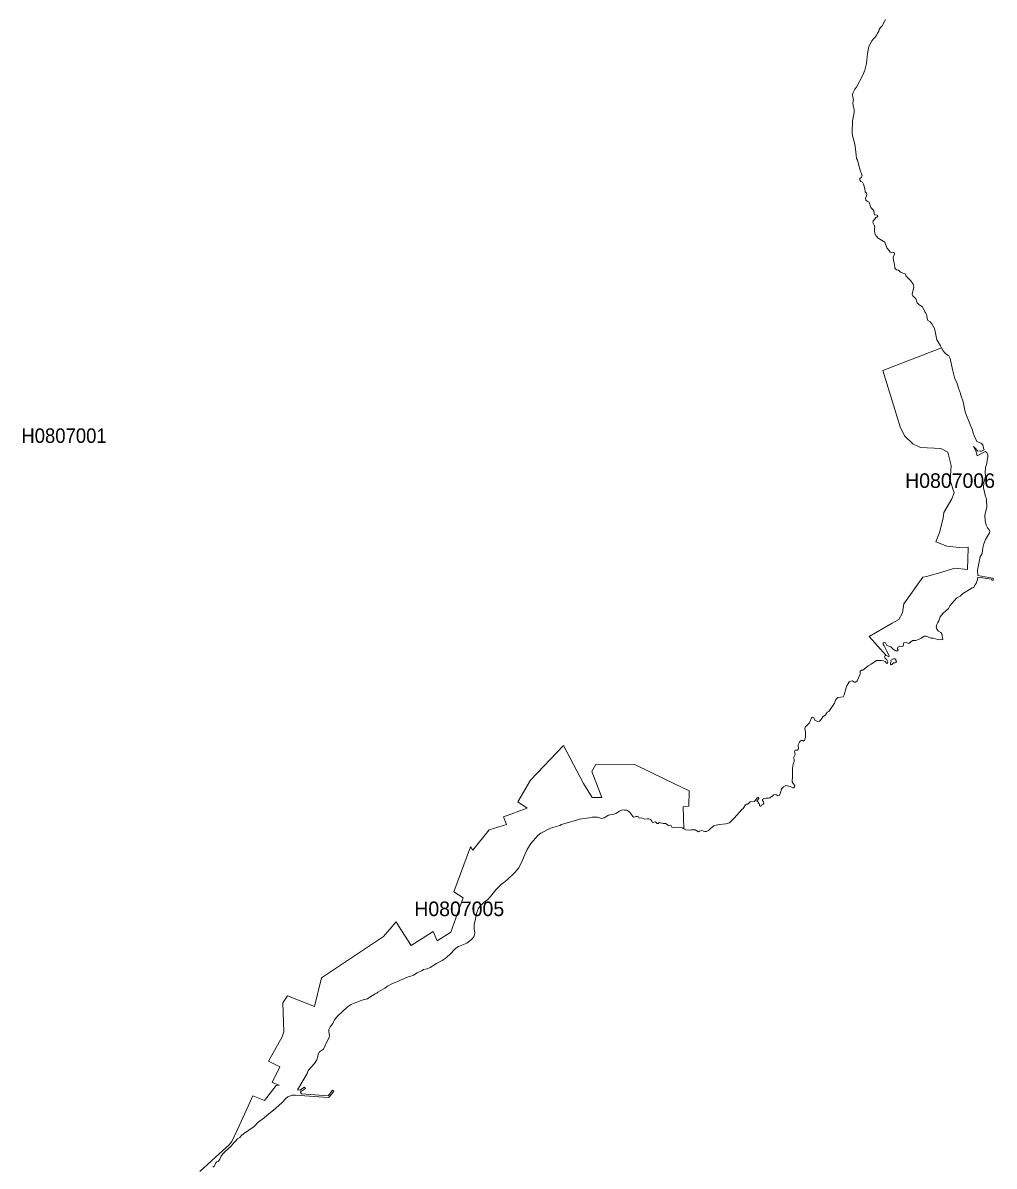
# Model space of a CAD drawing. Extents: x 369010 to 739155, y 6377141 to 6616555.
# Drawn here: x 386985 to 393656, y 6424081 to 6431932 of the extents above; entities that cross this region are included whole.
import ezdxf
from ezdxf.enums import TextEntityAlignment as Align

# ---------------------------------------------------------------- set-up
doc = ezdxf.new("R2010")
doc.units = 0
doc.header["$LTSCALE"] = 40
doc.layers.add('1', color=7, linetype='Continuous', lineweight=13)
doc.layers.add('2', color=7, linetype='Continuous')

msp = doc.modelspace()

# ---------------------------------------------------------------- linework, layer by layer
at = {"layer": '1'}
for points in [[(392739.34, 6430841.74), (392732.06, 6430851.17), (392733.88, 6430862.1), (392745.63, 6430872.19), (392748.78, 6430882.12), (392732.39, 6430927.14), (392716.83, 6430988.87), (392710.38, 6431001.12), (392706.41, 6431045.14), (392698.63, 6431098.27), (392682.24, 6431155.2), (392679.6, 6431181.35), (392682.91, 6431256.33), (392693.83, 6431318.56), (392694.82, 6431339.91), (392687.04, 6431363.08), (392685.39, 6431382.28), (392690.52, 6431406.11), (392686.05, 6431421.67), (392683.07, 6431438.22), (392687.04, 6431454.6), (392698.63, 6431476.94), (392711.21, 6431490.18), (392752.75, 6431572.11), (392767.81, 6431608.02), (392779.23, 6431652.87), (392785.68, 6431721.23), (392795.45, 6431770.38), (392814.81, 6431808.61), (392826.73, 6431822.52), (392837.16, 6431830.79), (392849.4, 6431848.67), (392853.54, 6431861.91), (392863.3, 6431875.15), (392866.45, 6431886.23), (392874.23, 6431899.14), (392887.47, 6431912.05), (392908.82, 6431955.08)], [(392797.1, 6427717.69), (392955.16, 6427810.53), (393000.67, 6427834.53), (393025.33, 6427880.87), (393036.42, 6427942.27), (393165.02, 6428126.65), (393190.51, 6428129.29), (393288.48, 6428157.6), (393382.66, 6428187.55), (393472.03, 6428178.61), (393478.32, 6428324.26), (393477.99, 6428332.7), (393414.43, 6428328.89), (393330.03, 6428338.99), (393255.55, 6428367.45), (393279.38, 6428431.5), (393304.54, 6428531.63), (393310.33, 6428570.53), (393364.45, 6428663.21), (393381, 6428703.92), (393352.87, 6428788.66), (393360.64, 6428891.61), (393337.14, 6428983.13), (393288.65, 6429009.94), (393148.8, 6429016.73), (393097.16, 6429041.72), (393040.56, 6429096.17), (393010.77, 6429157.9), (392890.78, 6429543.86), (393294.11, 6429699.93), (393294.28, 6429699.93), (393287, 6429713.17), (393272.27, 6429742.3), (393261.34, 6429756.2), (393251.25, 6429812.14), (393245.12, 6429833.82), (393228.74, 6429864.44), (393215.99, 6429878.17), (393199.61, 6429887.94), (393193.49, 6429913.1), (393193.49, 6429923.85), (393187.03, 6429937.59), (393178.59, 6429948.35), (393163.2, 6429982.94), (393140.03, 6429995.68), (393126.46, 6430008.59), (393118.35, 6430036.07), (393097.16, 6430056.42), (393093.19, 6430069.83), (393099.48, 6430098.3), (393102.95, 6430119.31), (393100.47, 6430137.52), (393084.25, 6430160.52), (393050.49, 6430192.63), (393045.03, 6430209.02), (393027.98, 6430212.66), (393013.42, 6430220.11), (392999.68, 6430233.02), (392984.62, 6430235.33), (392972.87, 6430248.57), (392972.21, 6430275.05), (392965.09, 6430301.2), (392961.95, 6430324.54), (392970.39, 6430341.09), (392970.72, 6430349.36), (392963.93, 6430354), (392951.85, 6430352.67), (392940.93, 6430356.81), (392931.49, 6430372.04), (392919.25, 6430387.93), (392904.02, 6430425.5), (392858.84, 6430454.29), (392845.76, 6430470.02), (392837.16, 6430485.24), (392833.51, 6430503.45), (392833.18, 6430519.83), (392835.5, 6430532.25), (392832.52, 6430543.83), (392823.25, 6430561.87), (392823.91, 6430573.29), (392834.84, 6430582.73), (392841.95, 6430594.64), (392850.4, 6430597.79), (392857.18, 6430604.9), (392854.2, 6430610.53), (392834.84, 6430614.67), (392828.38, 6430639), (392822.92, 6430649.59), (392808.69, 6430663.82), (392797.93, 6430700.73), (392783.7, 6430706.52), (392775.42, 6430714.63), (392773.11, 6430725.89), (392781.88, 6430750.22), (392778.24, 6430762.13), (392770.13, 6430771.57), (392766.65, 6430794.9), (392757.22, 6430825.19), (392750.76, 6430836.94), (392739.34, 6430841.74)], [(393294.28, 6429699.93), (393294.11, 6429699.93), (392890.78, 6429543.86), (393010.77, 6429157.9), (393040.56, 6429096.17), (393097.16, 6429041.72), (393148.8, 6429016.73), (393288.65, 6429009.94), (393337.14, 6428983.13), (393360.64, 6428891.61), (393352.87, 6428788.66), (393381, 6428703.92), (393364.45, 6428663.21), (393310.33, 6428570.53), (393304.54, 6428531.63), (393279.38, 6428431.5), (393255.55, 6428367.45), (393330.03, 6428338.99), (393414.43, 6428328.89), (393477.99, 6428332.7), (393478.32, 6428324.26), (393472.03, 6428178.61), (393382.66, 6428187.55), (393288.48, 6428157.6), (393190.51, 6428129.29), (393165.02, 6428126.65), (393036.42, 6427942.27), (393025.33, 6427880.87), (393000.67, 6427834.53), (392955.16, 6427810.53), (392797.1, 6427717.69), (392914.61, 6427587.6), (392916.27, 6427587.6), (392932.65, 6427577.83), (392935.13, 6427584.46), (392924.71, 6427600.84), (392918.91, 6427617.39), (392900.71, 6427653.47), (392893.43, 6427662.41), (392893.26, 6427673.33), (392900.71, 6427676.48), (392908.98, 6427673.66), (392919.25, 6427656.28), (392945.73, 6427648.34), (392961.95, 6427631.46), (392980.65, 6427620.2), (392993.39, 6427619.71), (392995.54, 6427626.33), (392992.4, 6427633.28), (392993.39, 6427644.2), (393006.96, 6427650.82), (393022.52, 6427650.16), (393029.8, 6427652.81), (393032.28, 6427668.53), (393036.26, 6427674.82), (393049.17, 6427676.14), (393069.52, 6427669.19), (393094.84, 6427691.37), (393117.85, 6427690.38), (393128.77, 6427696.34), (393156.41, 6427705.93), (393169.65, 6427718.68), (393174.62, 6427720.66), (393189.68, 6427720.5), (393220.96, 6427707.76), (393237.18, 6427706.43), (393269.45, 6427696.83), (393292.13, 6427694.85), (393303.55, 6427697.83), (393297.26, 6427736.39), (393290.14, 6427746.32), (393274.25, 6427754.43), (393261.18, 6427768.16), (393258.53, 6427784.22), (393262.17, 6427800.11), (393267.96, 6427815), (393275.74, 6427826.42), (393286, 6427852.74), (393306.03, 6427878.39), (393341.45, 6427911.33), (393352.37, 6427928.04), (393397.88, 6427980.67), (393421.55, 6427995.9), (393437.93, 6428010.46), (393504.14, 6428052.67), (393515.23, 6428055.48), (393522.51, 6428069.71), (393531.44, 6428082.46), (393542.37, 6428109.76), (393544.19, 6428125.32), (393638.36, 6428111.09), (393640.68, 6428104.97), (393648.79, 6428104.14), (393649.78, 6428118.87), (393619.99, 6428122.67), (393544.68, 6428136.91), (393541.54, 6428173.15), (393560.24, 6428264.84), (393572.82, 6428288.67), (393577.95, 6428327.24)], [(393577.95, 6428327.24), (393584.41, 6428354.21), (393596.82, 6428385), (393624.62, 6428430.01), (393626.94, 6428439.28), (393622.31, 6428451.36), (393609.23, 6428465.43), (393601.78, 6428483.31), (393593.67, 6428512.93), (393591.19, 6428550.34), (393606.42, 6428607.6), (393603.77, 6428657.25), (393600.96, 6428670), (393596.32, 6428679.59), (393581.59, 6428739.18), (393584.24, 6428775.42), (393591.85, 6428799.59), (393595.49, 6428818.12), (393593.01, 6428844.6), (393596.32, 6428878.2), (393605.92, 6428906.17), (393608.07, 6428931), (393612.21, 6428946.22), (393612.04, 6428962.44), (393605.09, 6428980.81), (393593.67, 6428987.43), (393538.23, 6428958.8), (393536.08, 6428970.88), (393528.8, 6428993.72), (393513.57, 6429021.86), (393525.82, 6429012.42), (393540.55, 6428993.39), (393558.92, 6428989.91), (393568.68, 6428990.74), (393587.55, 6429001), (393581.59, 6429010.44), (393577.29, 6429034.27), (393566.37, 6429045.52), (393536.24, 6429056.78), (393520.69, 6429091.04), (393508.94, 6429123.15), (393506.62, 6429135.56), (393466.24, 6429234.86), (393457.46, 6429260.35), (393443.07, 6429330.19), (393425.69, 6429374.38), (393424.86, 6429386.63), (393409.96, 6429424.03), (393399.54, 6429461.93), (393385.97, 6429487.42), (393369.08, 6429551.97), (393353.69, 6429627.6), (393344.92, 6429644.81), (393336.15, 6429649.61), (393316.79, 6429665.34), (393306.03, 6429678.74), (393294.28, 6429699.93)], [(392044.56, 6426568.59), (392044.39, 6426556.51), (392048.36, 6426553.03), (392055.31, 6426553.53), (392060.94, 6426561.31), (392069.05, 6426566.61), (392074.35, 6426574.22), (392071.53, 6426583.32), (392064.25, 6426591.1), (392065.41, 6426599.54), (392071.37, 6426604.34), (392089.41, 6426606.99), (392097.35, 6426609.14), (392105.3, 6426608.48), (392114.07, 6426611.13), (392131.78, 6426621.39), (392142.2, 6426630.32), (392155.11, 6426632.48), (392169.18, 6426623.7), (392179.77, 6426625.69), (392187.72, 6426642.9), (392194.67, 6426671.37), (392207.91, 6426685.27), (392225.29, 6426695.86), (392254.42, 6426687.92), (392271.96, 6426678.49), (392280.4, 6426679.81), (392285.53, 6426686.1), (392286.36, 6426695.86), (392275.1, 6426708.77), (392268.32, 6426720.52), (392270.97, 6426758.92), (392271.46, 6426814.53), (392275.77, 6426841.18), (392281.23, 6426860.71), (392281.23, 6426874.94), (392277.75, 6426885.86), (392289.01, 6426908.21), (392285.03, 6426927.57), (392289.01, 6426937.83), (392304.73, 6426938.33), (392312.84, 6426946.77), (392309.69, 6426974.24), (392318.13, 6426992.94), (392325.58, 6427001.05), (392331.04, 6427004.36), (392340.81, 6427004.2), (392346.77, 6426999.4), (392352.72, 6427003.04), (392359.68, 6427026.71), (392361, 6427060.3), (392356.37, 6427085.79), (392358.35, 6427095.56), (392387.48, 6427126.01), (392401.71, 6427160.27), (392407.84, 6427164.74), (392413.96, 6427162.75), (392427.37, 6427142.39), (392444.41, 6427134.95), (392455.17, 6427137.76), (392467.42, 6427148.52), (392478.84, 6427166.39), (392497.04, 6427181.12), (392509.46, 6427199), (392519.22, 6427203.63), (392558.45, 6427260.56), (392566.89, 6427281.42), (392573.01, 6427289.53), (392581.45, 6427298.3), (392618.19, 6427304.42), (392625.97, 6427316.84), (392636.07, 6427359.37), (392643.85, 6427380.22), (392660.73, 6427406.7), (392669.5, 6427412.33), (392681.91, 6427412.66), (392693.83, 6427404.22), (392702.6, 6427404.55), (392714.19, 6427412.99), (392736.03, 6427459.5), (392734.54, 6427474.06), (392736.03, 6427480.85), (392744.8, 6427485.98), (392754.73, 6427487.3), (392764, 6427493.43), (392790.81, 6427517.92), (392811.01, 6427528.85), (392846.75, 6427554), (392880.35, 6427554), (392896.24, 6427551.02), (392907.33, 6427545.89), (392916.43, 6427534.8), (392923.88, 6427533.65), (392924.71, 6427543.24), (392918.58, 6427557.15), (392906.17, 6427569.56), (392902.53, 6427578.99), (392907, 6427587.6), (392914.61, 6427587.6), (392797.1, 6427717.69)], [(388199.57, 6424044.16), (388333.46, 6424165.97), (388400.82, 6424227.37), (388420.35, 6424251.37), (388459.24, 6424333.63), (388544.81, 6424519.16), (388564.34, 6424564.5), (388644.28, 6424531.4), (388724.71, 6424634.02), (388744.57, 6424637.82), (388697.9, 6424654.54), (388749.87, 6424762.94), (388672.58, 6424801.17), (388764.6, 6424969.33), (388777.18, 6425003.75), (388770.72, 6425202.52), (388801.51, 6425251.01), (388987.53, 6425176.87), (389036.19, 6425375.47), (389461.37, 6425658.98), (389547.93, 6425759.77), (389563.98, 6425730.48), (389652.2, 6425595.92), (389803.3, 6425692.25), (389829.78, 6425629.19), (389923.95, 6425689.1), (389981.88, 6425848.15), (390009.85, 6425924.78), (389943.65, 6425964.67), (390058.84, 6426273.33), (390076.05, 6426250.82), (390186.77, 6426389.85), (390305.44, 6426427.75), (390286.24, 6426479.22), (390448.77, 6426539.79), (390385.05, 6426583.98), (390471.44, 6426732.27), (390697.68, 6426970.27), (390834.23, 6426708.44), (390893.81, 6426612.78), (390960.67, 6426612.62), (390891.99, 6426791.86), (390919.29, 6426838.53), (391192.87, 6426837.87), (391393.79, 6426737.74), (391559.96, 6426658.79), (391557.97, 6426552.21), (391520.07, 6426548.57), (391523.55, 6426397.96), (391539.11, 6426390.84), (391561.95, 6426387.7), (391574.36, 6426391.5), (391602.99, 6426391.5), (391624.18, 6426377.27), (391633.11, 6426382.23), (391648.67, 6426385.54), (391659.43, 6426380.74), (391669.36, 6426379.42), (391680.45, 6426380.25), (391695.84, 6426387.86), (391706.93, 6426398.95), (391731.42, 6426418.81), (391745.99, 6426423.28), (391768.33, 6426427.09), (391813.18, 6426432.22), (391837.01, 6426439), (391869.29, 6426470.28), (391923.24, 6426530.53), (391932.01, 6426536.81), (391947.9, 6426561.64), (391954.03, 6426566.27), (391963.79, 6426567.76), (391980.18, 6426583.98), (392009.14, 6426586.13), (392029, 6426611.13), (392036.45, 6426614.11), (392040.09, 6426607.98), (392026.35, 6426587.62), (392036.94, 6426579.68), (392034.79, 6426571.41), (392044.56, 6426568.59)], [(391329.74, 6426445.62), (391341.83, 6426434.2), (391349.44, 6426434.7), (391355.73, 6426440.82), (391381.38, 6426435.2), (391398.43, 6426434.2), (391409.85, 6426426.26), (391419.28, 6426421.29), (391434.01, 6426422.78), (391442.62, 6426409.05), (391455.53, 6426403.25), (391493.43, 6426408.05), (391512.3, 6426403.25), (391523.55, 6426397.96), (391520.07, 6426548.57), (391557.97, 6426552.21), (391559.96, 6426658.79), (391393.79, 6426737.74), (391192.87, 6426837.87), (390919.29, 6426838.53), (390891.99, 6426791.86), (390960.67, 6426612.62), (390893.81, 6426612.78), (390834.23, 6426708.44), (390697.68, 6426970.27), (390471.44, 6426732.27), (390385.05, 6426583.98), (390448.77, 6426539.79), (390286.24, 6426479.22), (390305.44, 6426427.75), (390186.77, 6426389.85), (390076.05, 6426250.82), (390058.84, 6426273.33), (389943.65, 6425964.67), (390009.85, 6425924.78)], [(389050.09, 6424885.58), (389078.89, 6424947.81), (389088.82, 6424963.7), (389091.47, 6424978.43), (389085.51, 6425004.08), (389087, 6425020.63), (389094.94, 6425037.85), (389113.48, 6425061.18), (389124.9, 6425087), (389145.09, 6425111.99), (389211.79, 6425172.9), (389239.93, 6425190.44), (389260.28, 6425200.04), (389322.84, 6425223.04), (389351.81, 6425231.15), (389367.36, 6425242.08), (389404.27, 6425263.92), (389416.35, 6425269.88), (389421.98, 6425275.18), (389471.13, 6425303.31), (389488.84, 6425317.71), (389513.83, 6425331.95), (389530.22, 6425336.91), (389573.75, 6425355.28), (389604.86, 6425370.34), (389615.79, 6425374.15), (389630.85, 6425381.43), (389642.1, 6425383.75), (389666.76, 6425393.02), (389692.41, 6425408.08), (389726.51, 6425423.8), (389735.61, 6425431.08), (389761.26, 6425436.54), (389783.28, 6425444.98), (389826.64, 6425472.62), (389865.03, 6425492.82), (389886.05, 6425506.39), (389917.5, 6425535.35), (389959.04, 6425579.04), (389977.91, 6425589.8), (390034.01, 6425613.47), (390065.29, 6425637.47), (390081.35, 6425656.83), (390087.14, 6425669.57), (390088.13, 6425682.81), (390084.99, 6425713.1), (390084.99, 6425741.73), (390092.44, 6425778.97), (390100.38, 6425816.21), (390111.3, 6425848.32), (390129.01, 6425871.99), (390164.93, 6425902.27), (390174.86, 6425910.38), (390195.88, 6425932.73), (390233.28, 6425979.56), (390271.35, 6426017.96), (390287.07, 6426028.39), (390310.24, 6426047.09), (390364.36, 6426096.91), (390390.84, 6426129.34), (390416.66, 6426181.31), (390433.87, 6426225.5), (390448.27, 6426255.46), (390473.43, 6426296.67), (390522.09, 6426350.62), (390543.27, 6426367.01), (390608.15, 6426401.93), (390671.87, 6426421.29), (390684.94, 6426427.25), (390787.22, 6426458.03), (390806.92, 6426464.82), (390874.61, 6426472.76), (390895.96, 6426477.07), (390931.87, 6426477.73), (390958.19, 6426467.63), (390978.38, 6426472.27), (391006.18, 6426491.3), (391042.93, 6426497.26), (391057.82, 6426502.89), (391081.49, 6426519.44), (391095.89, 6426526.22), (391105.98, 6426528.71), (391116.24, 6426525.89), (391132.46, 6426525.89), (391146.7, 6426517.62), (391158.28, 6426506.2), (391173.01, 6426481.54), (391181.12, 6426477.9), (391198.17, 6426482.86), (391206.44, 6426483.03), (391212.57, 6426479.55), (391217.2, 6426470.28), (391232.76, 6426472.27), (391255.93, 6426463.99), (391274.3, 6426466.97), (391285.06, 6426467.3), (391298.63, 6426459.19), (391304.75, 6426452.08), (391307.9, 6426440.99), (391329.74, 6426445.62)], [(390009.85, 6425924.78), (389981.88, 6425848.15), (389923.95, 6425689.1), (389829.78, 6425629.19), (389803.3, 6425692.25), (389652.2, 6425595.92), (389563.98, 6425730.48), (389547.93, 6425759.77), (389461.37, 6425658.98), (389036.19, 6425375.47), (388987.53, 6425176.87), (388801.51, 6425251.01), (388770.72, 6425202.52), (388777.18, 6425003.75), (388764.6, 6424969.33), (388672.58, 6424801.17), (388749.87, 6424762.94), (388697.9, 6424654.54), (388744.57, 6424637.82), (388724.71, 6424634.02), (388644.28, 6424531.4), (388564.34, 6424564.5), (388544.81, 6424519.16), (388459.24, 6424333.63), (388420.35, 6424251.37), (388400.82, 6424227.37), (388333.46, 6424165.97), (388199.57, 6424044.16)], [(388290.43, 6424075.11), (388301.85, 6424083.05), (388310.62, 6424104.57), (388317.41, 6424111.68), (388327.83, 6424115.16), (388338.43, 6424129.06), (388347.53, 6424150.58), (388357.13, 6424165.31), (388376.82, 6424184.67), (388416.05, 6424219.26), (388429.95, 6424237.3), (388444.68, 6424253.69), (388458.75, 6424267.92), (388474.47, 6424278.51), (388485.89, 6424291.92), (388499.13, 6424303.67), (388572.61, 6424354.64), (388601.91, 6424383.94), (388640.64, 6424410.75), (388647.59, 6424418.36), (388721.57, 6424480.1), (388766.75, 6424517.33), (388791.74, 6424545.8), (388804.82, 6424557.72), (388833.28, 6424568.14), (388856.29, 6424568.14), (389081.54, 6424553.41), (389089.32, 6424554.57), (389120.93, 6424596.61), (389110.5, 6424602.9), (389081.37, 6424564.5), (388898.49, 6424578.41), (388893.19, 6424585.19), (388892.7, 6424592.31), (388925.63, 6424613.66), (388919.84, 6424622.6), (388887.07, 6424604.06), (388872.01, 6424605.88), (388936.89, 6424717.93), (388945.33, 6424738.45), (388987.86, 6424786.11), (389003.92, 6424810.77), (389011.03, 6424834.61), (389013.19, 6424849.83), (389021.63, 6424865.39), (389050.09, 6424885.58)]]:
    msp.add_lwpolyline(points, dxfattribs=at)
msp.add_lwpolyline([(392961.61, 6427564.76), (392945.56, 6427555.16), (392949.04, 6427545.73), (392942.91, 6427536.29), (392942.75, 6427527.69), (392947.71, 6427524.54), (392952.84, 6427525.04), (392965.26, 6427536.46), (392976.51, 6427536.46), (392982.8, 6427539.77), (392984.95, 6427545.56), (392981.31, 6427551.02), (392980.65, 6427560.62), (392972.87, 6427564.59)], close=True, dxfattribs=at)

# ---------------------------------------------------------------- texts
at = {"layer": '2', "width": 0.95}
msp.add_text('H0807001', height=100, dxfattribs=at).set_placement((387267.56, 6429047.32), align=Align.CENTER)
at = {"layer": '2'}
for s, p in [('H0807006', (393352.86, 6428738.66)), ('H0807005', (389981.88, 6425798.15))]:
    msp.add_text(s, height=100, dxfattribs=at).set_placement(p, align=Align.CENTER)

doc.saveas('drawing.dxf')
